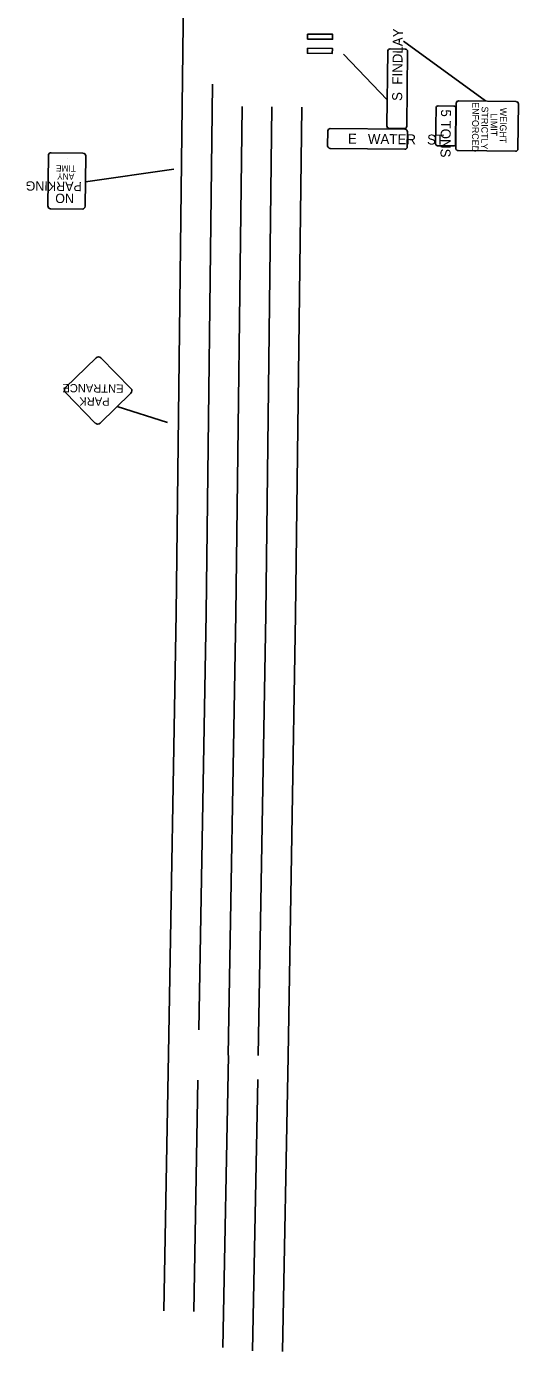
# Model space of a CAD drawing. Extents: x 1652376 to 1652707, y 605933 to 608571.
# Drawn here: x 1652456 to 1652653, y 605933 to 606465 of the extents above; entities that cross this region are included whole.
import ezdxf

# ---------------------------------------------------------------- set-up
doc = ezdxf.new("R2010")
doc.units = 0
for name, color, linetype in [('_CIVIL_CONSTRUCTION', 7, 'Continuous'), ('GE_P_Alignment', 7, 'Continuous'), ('PM_P_CL_Double_Solid', 7, 'Continuous'), ('PV_P_EOP', 7, 'Continuous'), ('RW_P_Fee_RW', 7, 'Continuous'), ('SH_Border', 7, 'Continuous'), ('SN_P_Text', 7, 'Continuous'), ('UT_X_Misc_Cells', 7, 'Continuous')]:
    doc.layers.add(name, color=color, linetype=linetype)

msp = doc.modelspace()

# ---------------------------------------------------------------- linework, layer by layer
at = {"layer": '_CIVIL_CONSTRUCTION'}
for points in [[(1652568.82, 606462.12), (1652568.8, 606460.12), (1652578.81, 606460.03), (1652578.83, 606462.03)], [(1652568.77, 606456.45), (1652568.75, 606454.42), (1652578.72, 606454.33), (1652578.74, 606456.36)]]:
    msp.add_lwpolyline(points, close=True, dxfattribs=at)
at = {"layer": 'GE_P_Alignment'}
for points in [[(1652525.14, 606061.86), (1652528.01, 606229.23), (1652530.58, 606441.93)], [(1652548.96, 606051.58), (1652552, 606228.88), (1652554.48, 606432.85)]]:
    msp.add_lwpolyline(points, dxfattribs=at)
at = {"layer": 'PM_P_CL_Double_Solid'}
msp.add_line((1652518.48, 606433.28), (1652522.93, 606800.85), dxfattribs=at)
for points in [[(1652512.97, 606052.19), (1652516.01, 606229.41), (1652518.48, 606433.28)], [(1652560.96, 606051.37), (1652564, 606228.71), (1652566.47, 606432.7)]]:
    msp.add_lwpolyline(points, dxfattribs=at)
at = {"layer": 'PV_P_EOP'}
msp.add_lwpolyline([(1652536.96, 606051.78), (1652540.01, 606229.06), (1652542.48, 606432.99)], dxfattribs=at)
at = {"layer": 'RW_P_Fee_RW'}
for p, q in [((1652511.12, 605948.95), (1652512.97, 606052.19)), ((1652534.82, 605934.29), (1652537.02, 606051.59)), ((1652558.73, 605932.62), (1652560.96, 606051.37)), ((1652523.12, 605948.74), (1652524.78, 606041.62)), ((1652546.73, 605932.85), (1652548.78, 606041.9))]:
    msp.add_line(p, q, dxfattribs=at)
at = {"layer": 'SH_Border'}
for p, q in [((1652620.21, 606418.03), (1652620.37, 606432.43)), ((1652621.17, 606433.22), (1652627.57, 606433.15)), ((1652628.37, 606432.34), (1652628.21, 606417.94)), ((1652627.4, 606417.15), (1652621, 606417.22)), ((1652472.23, 606412.06), (1652472.23, 606412.06))]:
    msp.add_line(p, q, dxfattribs=at)
for points in [[(1652600.96, 606455.18), (1652600.63, 606425.18)], [(1652601.97, 606456.17), (1652607.97, 606456.1)], [(1652608.63, 606425.09), (1652608.96, 606455.09)], [(1652628.27, 606416.28), (1652628.47, 606434.28)], [(1652629.48, 606435.27), (1652652.47, 606435.02)], [(1652653.46, 606434.01), (1652653.27, 606416.01)], [(1652607.92, 606423.83), (1652577.92, 606424.16)], [(1652601.62, 606424.17), (1652607.62, 606424.1)], [(1652576.91, 606423.17), (1652576.84, 606417.17)], [(1652608.91, 606422.82), (1652608.84, 606416.82)], [(1652464.72, 606413.3), (1652464.49, 606393.05)], [(1652478.6, 606414.27), (1652465.85, 606414.41)], [(1652479.49, 606392.88), (1652479.71, 606413.13)], [(1652577.83, 606416.16), (1652607.83, 606415.83)], [(1652652.25, 606415.02), (1652629.26, 606415.27)], [(1652465.61, 606391.91), (1652478.35, 606391.77)], [(1652471.57, 606320), (1652483.86, 606332.03)], [(1652485.84, 606332), (1652497.87, 606319.71)], [(1652483.57, 606305.72), (1652471.55, 606318.02)], [(1652497.85, 606317.73), (1652485.55, 606305.7)]]:
    msp.add_lwpolyline(points, dxfattribs=at)
for centre, radius, start, end in [((1652601.96, 606455.17), 1, 89.3709, 179.3709), ((1652607.96, 606455.1), 1, 359.3709, 89.3709), ((1652629.46, 606434.27), 1, 89.3709, 179.3709), ((1652652.46, 606434.02), 1, 359.3709, 89.3709), ((1652621.17, 606432.42), 0.8, 89.3709, 179.3709), ((1652627.57, 606432.35), 0.8, 359.3709, 89.3709), ((1652577.91, 606423.16), 1, 89.3709, 179.3709), ((1652601.63, 606425.17), 1, 179.3709, 269.3709), ((1652607.63, 606425.1), 1, 269.3709, 359.3709), ((1652607.91, 606422.83), 1, 359.3709, 89.3709), ((1652621.01, 606418.02), 0.8, 179.3709, 269.3709), ((1652627.41, 606417.95), 0.8, 269.3709, 359.3709), ((1652465.84, 606413.28), 1.12, 89.3709, 179.3709), ((1652478.59, 606413.14), 1.12, 359.3709, 89.3709), ((1652577.84, 606417.16), 1, 179.3709, 269.3709), ((1652607.84, 606416.83), 1, 269.3709, 359.3709), ((1652629.27, 606416.27), 1, 179.3709, 269.3709), ((1652652.27, 606416.02), 1, 269.3709, 359.3709), ((1652465.62, 606393.04), 1.12, 179.3709, 269.3709), ((1652478.37, 606392.9), 1.12, 269.3709, 359.3709), ((1652484.84, 606331.02), 1.4, 44.3709, 134.3709), ((1652472.55, 606319), 1.4, 134.3709, 224.3709), ((1652496.87, 606318.73), 1.4, 314.3709, 44.3709), ((1652484.58, 606306.7), 1.4, 224.3709, 314.3709)]:
    msp.add_arc(centre, radius, start, end, dxfattribs=at)
at = {"layer": 'UT_X_Misc_Cells'}
for p, q in [((1652640.25, 606435.23), (1652607.29, 606459.2)), ((1652600.75, 606435.73), (1652583.25, 606454.04)), ((1652515.1, 606407.84), (1652479.6, 606402.7)), ((1652492.37, 606312.36), (1652512.56, 606306.02))]:
    msp.add_line(p, q, dxfattribs=at)

# ---------------------------------------------------------------- texts
at = {"layer": 'SH_Border'}
for s, height, rotation, p in [('        S  FINDLAY', 4, 89.3709, (1652606.61, 606423.33)), ('5 TONS', 4, 269.3709, (1652622.36, 606431.84)), ('        E   WATER   ST', 4, 359.3709, (1652573.07, 606418.21)), ('TIME', 2.5, 179.3709, (1652475.77, 606409.3)), ('PARKING', 3.75, 179.3709, (1652478.17, 606402.71)), ('ANY', 2.5, 179.3709, (1652475.14, 606406.03)), ('NO', 3.75, 179.3709, (1652475.02, 606397.9)), ('ENTRANCE', 3.333, 179.3709, (1652494.89, 606321.25)), ('PARK', 3.333, 179.3709, (1652489.3, 606316.03))]:
    msp.add_text(s, height=height, rotation=rotation, dxfattribs=at).set_placement(p)
at = {"layer": 'SN_P_Text'}
for s, p in [('ENFORCED', (1652634.96, 606434.73)), ('STRICTLY', (1652638.66, 606433.01)), ('LIMIT', (1652642.34, 606430.21)), ('WEIGHT', (1652646.08, 606432.49))]:
    msp.add_text(s, height=2.667, rotation=269.3709, dxfattribs=at).set_placement(p)

doc.saveas('drawing.dxf')
